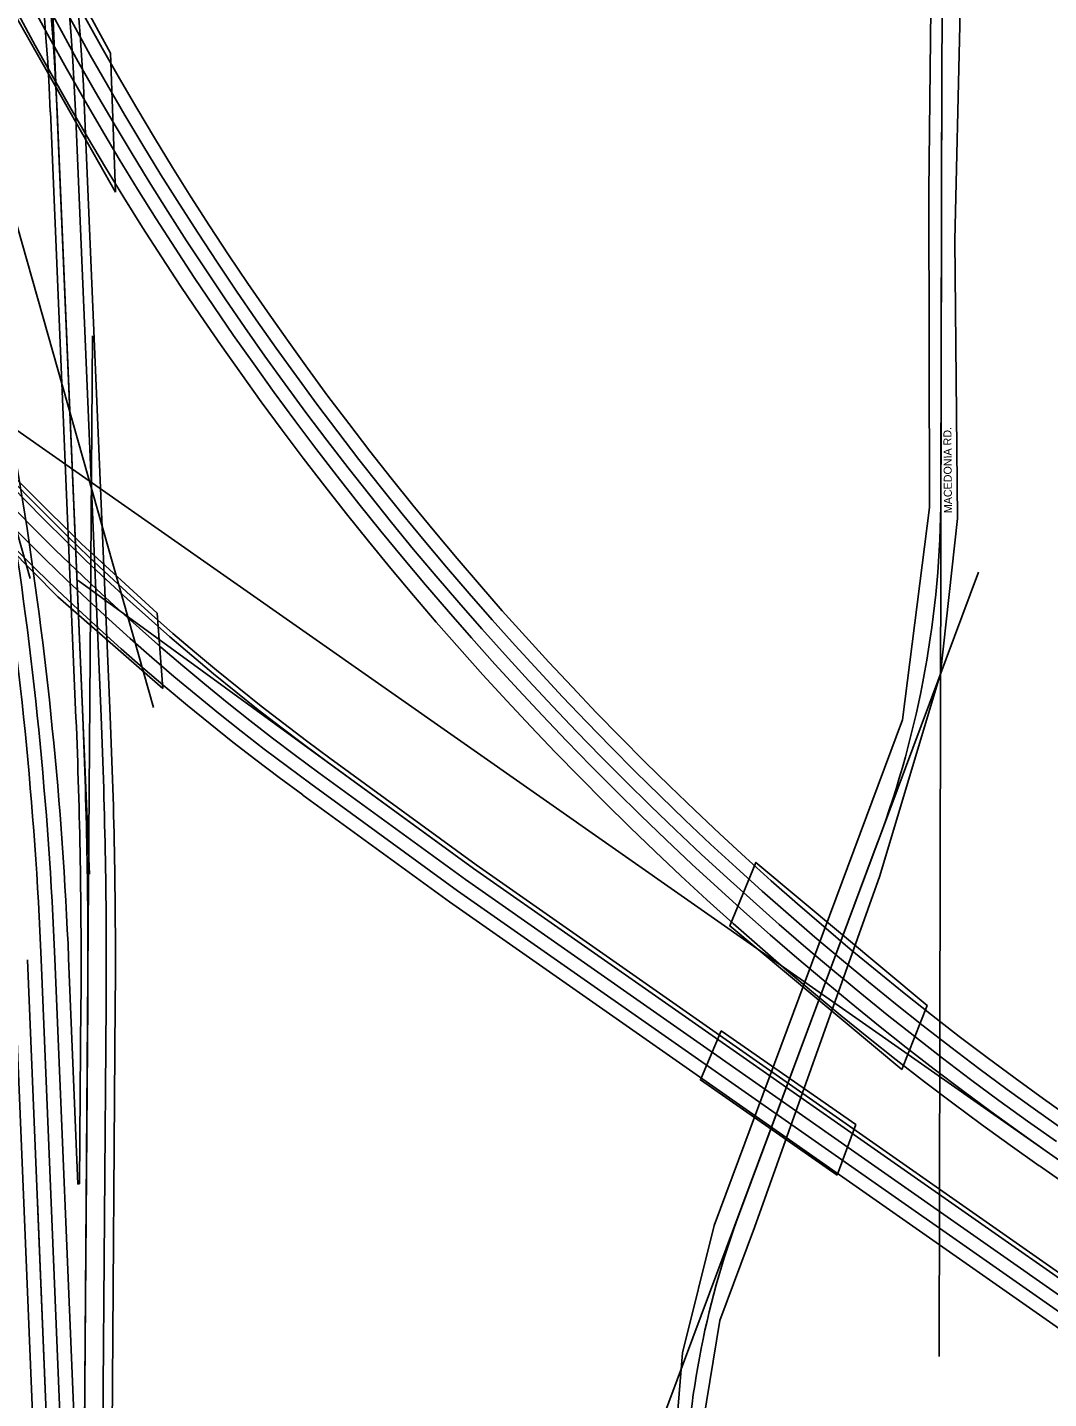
# Model space of a CAD drawing. Extents: x 227157 to 233208, y 434992 to 456232.
# Drawn here: x 229631 to 230524, y 436747 to 437946 of the extents above; entities that cross this region are included whole.
import ezdxf

# ---------------------------------------------------------------- set-up
doc = ezdxf.new("R2010")
doc.units = 0
for name, color, linetype in [('BR_X_Slab_Object', 7, 'Continuous'), ('Default', 7, 'Continuous'), ('GE_X_Alignment', 7, 'Continuous'), ('PM_X_Edge_Line', 7, 'Continuous'), ('PM_X_Lane_Line', 7, 'Continuous'), ('PV_X_EOP', 7, 'Continuous'), ('SV_X_Text_Name', 7, 'Continuous')]:
    doc.layers.add(name, color=color, linetype=linetype)

msp = doc.modelspace()

# ---------------------------------------------------------------- linework, layer by layer
at = {"layer": 'BR_X_Slab_Object'}
for points in [[(229708, 437802.5), (229703.6, 437923.9), (229654, 438015.2), (229586.4, 438149.4), (229593.7, 438003.8)], [(229749.3, 437368.1), (229744.4, 437434.1), (229678.2, 437494.9), (229589.3, 437582.9), (229466.6, 437730.1), (229358.1, 437886.5), (229350.6, 437901.6), (229359.7, 437802.1), (229384.2, 437764.6), (229474.2, 437643.4), (229571.5, 437535.3), (229657.5, 437448.5)], [(230395.3, 437034.9), (230417.4, 437091), (230267.7, 437216.1), (230244.9, 437160.5)], [(230338.7, 436942.6), (230355, 436986.7), (230237.4, 437068.7), (230219.2, 437025.8)]]:
    msp.add_lwpolyline(points, close=True, dxfattribs=at)
at = {"layer": 'Default'}
for p, q in [((230430.3, 437918.6), (230436.5, 438464.1)), ((230430.3, 437918.6), (230436.5, 438464.1)), ((230428, 436783.8), (230430.3, 437918.6)), ((230429.5, 437537.3), (230430.3, 437918.6))]:
    msp.add_line(p, q, dxfattribs=at)
at = {"layer": 'GE_X_Alignment'}
for p, q in [((229741.1, 437351.7), (227977.9, 443563.5)), ((229633.3, 437464.5), (227927.6, 443466.1)), ((229633.3, 438432), (229685, 437205.8)), ((233187.2, 435095.9), (229325.8, 437801.3)), ((229679.6, 436542.4), (229687.8, 437676.6)), ((230184.4, 436724.3), (230462.3, 437469.9)), ((230020.9, 437210.8), (229675.1, 437462.8)), ((230020.9, 437210.8), (233138.8, 435026.8)), ((229674.1, 436083.3), (229639.6, 436919.4))]:
    msp.add_line(p, q, dxfattribs=at)
for centre, radius, start, end in [((231114.1, 438979.7), 2073.4, 189.9375, 233.9115), ((227564.8, 437784.8), 2093.9, 2.412, 21.422), ((232176.7, 439321.6), 2881, 195.846, 234.9841), ((229558.4, 437539), 871.1, 339.5614, 359.8863), ((224602, 437129.1), 5081.8, 359.5847, 2.412), ((230965.4, 436643.8), 759.9, 159.5614, 179.3497)]:
    msp.add_arc(centre, radius, start, end, dxfattribs=at)
at = {"layer": 'PM_X_Edge_Line'}
for p, q in [((230430.3, 437918.6), (230436.5, 438464.1)), ((230429.5, 437537.3), (230430.3, 437918.6)), ((229679.2, 437343), (229656.9, 437872.9)), ((229695.2, 437343.7), (229672.9, 437873.6)), ((230020.9, 437210.8), (229892.8, 437304.1)), ((230006.9, 437191.2), (229878.7, 437284.7)), ((230253.3, 436909.2), (230374.7, 437234.9)), ((233138.8, 435026.8), (230020.9, 437210.8)), ((233125.1, 435007.1), (230006.9, 437191.2)), ((229674.1, 436083.3), (229630.9, 437130.8)), ((229679.2, 436543.1), (229654.9, 437131.8)), ((229679.6, 436542.4), (229683.6, 437092.3)), ((229695.6, 436542.2), (229699.6, 437092.2))]:
    msp.add_line(p, q, dxfattribs=at)
for centre, radius, start, end in [((231114.1, 438979.7), 2073.4, 189.9375, 233.9115), ((231114.1, 438979.7), 2097.4, 189.9375, 233.9115), ((227564.8, 437784.8), 2093.9, 2.412, 21.422), ((227564.8, 437784.8), 2109.9, 2.412, 21.422), ((232176.7, 439321.6), 2857, 195.846, 234.9841), ((232176.7, 439321.6), 2881, 195.846, 234.9841), ((226248.5, 436991.1), 3409.3, 2.3646, 15.8658), ((229558.4, 437539), 871.1, 339.5614, 359.8863), ((224602, 437129.1), 5081.8, 359.5847, 2.412), ((224602, 437129.1), 5097.8, 359.5847, 2.412), ((230965.4, 436643.8), 759.9, 159.5614, 179.3497)]:
    msp.add_arc(centre, radius, start, end, dxfattribs=at)
at = {"layer": 'PM_X_Lane_Line'}
for p, q in [((230013.9, 437201), (229885.7, 437294.4)), ((233132, 435016.9), (230013.9, 437201)), ((229642.9, 437131.3), (229686.1, 436083.9))]:
    msp.add_line(p, q, dxfattribs=at)
for centre, radius, start, end in [((231114.1, 438979.7), 2085.4, 189.9375, 233.9115), ((232176.7, 439321.6), 2869, 195.846, 234.9841), ((226248.5, 436991.1), 3397.3, 2.3646, 15.8658)]:
    msp.add_arc(centre, radius, start, end, dxfattribs=at)
at = {"layer": 'PV_X_EOP'}
for p, q in [((229673.2, 437342.7), (229650.9, 437872.6)), ((229703.2, 437344), (229680.9, 437873.9)), ((230023.2, 437214), (229895.2, 437307.4)), ((229999.9, 437181.5), (229871.6, 437275)), ((233141.1, 435030.1), (230023.2, 437214)), ((233118.2, 434997.3), (229999.9, 437181.5)), ((229662.1, 436082.8), (229618.9, 437130.3)), ((229675, 436934.7), (229666.8, 437132.3)), ((229676.4, 436935), (229677.6, 437092.3)), ((229703.6, 436542.2), (229707.6, 437092.1)), ((231014.7, 436600.9), (230515.6, 436950.6)), ((229675, 436934.7), (229676.4, 436935))]:
    msp.add_line(p, q, dxfattribs=at)
for points in [[(230231.3, 436898.5), (230395.9, 437340.7), (230419.4, 437526.4), (230418.9, 437803.2), (230425.9, 438441.8), (230421.2, 438596.6), (230417.1, 438716.3)], [(230440.4, 438711.7), (230447.9, 438345), (230443.5, 438215.8), (230446.1, 437948.1), (230441.7, 437760.3), (230443.9, 437516.9), (230429.2, 437381.2), (230376.1, 437204.3), (230266.4, 436896.8)], [(230218.2, 435005.6), (230207.8, 435660.4), (230198.5, 436046.8), (230192.3, 436562.5), (230196.7, 436701), (230203.7, 436787), (230231.3, 436898.5)], [(230266.4, 436896.8), (230236.3, 436815.4), (230221.6, 436726.6), (230223.6, 435999.2), (230229.4, 435637.6), (230240.2, 435006.5)]]:
    msp.add_lwpolyline(points, dxfattribs=at)
for centre, radius, start, end in [((231114.1, 438979.7), 2069.4, 189.9375, 233.9115), ((231114.1, 438979.7), 2109.4, 189.9375, 233.9115), ((227564.8, 437784.8), 2117.9, 2.412, 21.422), ((232176.7, 439321.6), 2845, 195.846, 234.9841), ((227564.8, 437784.8), 2087.9, 2.412, 21.422), ((232176.7, 439321.6), 2895, 195.846, 234.9841), ((226248.5, 436991.1), 3421.3, 2.3646, 15.8658), ((224602, 437129.1), 5075.8, 359.5847, 2.412), ((224602, 437129.1), 5105.8, 359.5847, 2.412)]:
    msp.add_arc(centre, radius, start, end, dxfattribs=at)

# ---------------------------------------------------------------- texts
at = {"layer": 'SV_X_Text_Name'}
msp.add_text('MACEDONIA RD.', height=7, rotation=90.4373, dxfattribs=at).set_placement((230439.2, 437521.6))

doc.saveas('drawing.dxf')
